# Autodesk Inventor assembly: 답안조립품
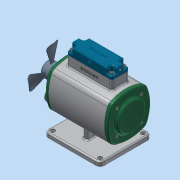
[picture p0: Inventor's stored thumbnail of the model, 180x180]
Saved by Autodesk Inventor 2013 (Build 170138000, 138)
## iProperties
Created: 2016-06
Part Number: 답안조립품
Document SubType Name: Assembly
Designer: Administrator
Mass: 3420.87 g
Surface Area: 2823.53 cm^2
Volume: 1020.99 cm^3
Density: 3.35053 g/cm^3
Author: Administrator
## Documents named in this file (19)
- C:\Users\Administrator\Desktop\360608V1015\답안조립품.iam
- C:\Users\Administrator\Desktop\360608V1015\15 스프링.ipt
- C:\Users\Administrator\Desktop\360608V1015\16 스프링.ipt
- C:\Users\Administrator\Desktop\360608V1015\17 스프링.ipt
- C:\Users\Administrator\Desktop\360608V1015\뒷커버.ipt
- C:\Users\Administrator\Desktop\360608V1015\멈춤나사 M4x5.ipt
- C:\Users\Administrator\Desktop\360608V1015\베어링 6203.ipt
- C:\Users\Administrator\Desktop\360608V1015\본체.ipt
- C:\Users\Administrator\Desktop\360608V1015\볼트 M4 x 12.ipt
- C:\Users\Administrator\Desktop\360608V1015\볼트 M4 x 16.ipt
- C:\Users\Administrator\Desktop\360608V1015\부시.ipt
- C:\Users\Administrator\Desktop\360608V1015\슬라이드.ipt
- C:\Users\Administrator\Desktop\360608V1015\앞커버.ipt
- C:\Users\Administrator\Desktop\360608V1015\오일실 17 30 8.ipt
- C:\Users\Administrator\Desktop\360608V1015\축.ipt
- C:\Users\Administrator\Desktop\360608V1015\키 - 5 x 5 x 18.ipt
- C:\Users\Administrator\Desktop\360608V1015\팬날개.ipt
- 팬날개.ipt
- C:\Users\Administrator\Desktop\360608V1015\헤더커버.ipt
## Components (6 placed, 5 different names)
1. 15 스프링:1
2. 16 스프링:1
3. 17 스프링:1
4. 7-베어링 6203:1
5. 헤더커버:1
6. 7-베어링 6203:2
